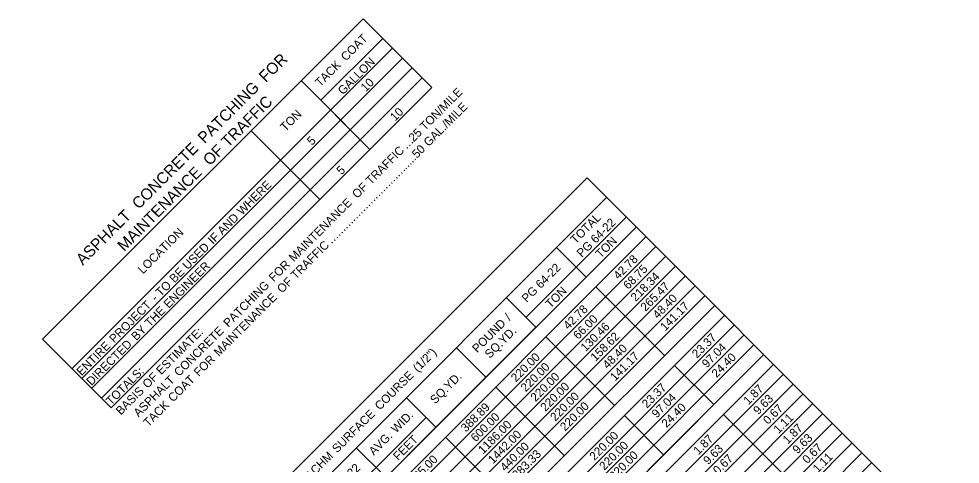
# Model space of a CAD drawing. Extents: x 1675667 to 1681231, y 227227 to 232694.
# Drawn here: x 1679139 to 1679800, y 230867 to 231180 of the extents above; entities that cross this region are included whole.
import ezdxf

# ---------------------------------------------------------------- set-up
doc = ezdxf.new("R2010")
doc.units = 0
doc.layers.add('Default', color=7, linetype='Continuous')

msp = doc.modelspace()

# ---------------------------------------------------------------- linework, layer by layer
at = {"layer": 'Default'}
for p, q in [((1679156.05, 230954.8), (1679381.12, 231179.93)), ((1679429.39, 231131.68), (1679381.12, 231179.93)), ((1679394.91, 231166.14), (1679381.12, 231179.93)), ((1679351.48, 231122.7), (1679394.91, 231166.14)), ((1679176.73, 230934.12), (1679401.8, 231159.25)), ((1679415.59, 231145.46), (1679401.8, 231159.25)), ((1679183.63, 230927.23), (1679408.7, 231152.36)), ((1679190.52, 230920.34), (1679415.59, 231145.46)), ((1679197.42, 230913.44), (1679422.49, 231138.57)), ((1679385.96, 231088.24), (1679337.69, 231136.49)), ((1679429.39, 231131.68), (1679422.49, 231138.57)), ((1679204.31, 230906.55), (1679429.39, 231131.68)), ((1679385.96, 231088.24), (1679351.48, 231122.7)), ((1679350.8, 231053.07), (1679302.53, 231101.33)), ((1679350.8, 231053.07), (1679323.22, 231080.65)), ((1678525.01, 230054.56), (1679538.35, 231068.14)), ((1679800.36, 230806.19), (1679538.35, 231068.14)), ((1679800.36, 230806.19), (1679538.35, 231068.14)), ((1678778.69, 230280.72), (1679552.14, 231054.36)), ((1679495.62, 230970.24), (1679565.93, 231040.57)), ((1678559.49, 230020.09), (1679572.82, 231033.68)), ((1679432.2, 230893.02), (1679572.82, 231033.68)), ((1678566.38, 230013.2), (1679579.72, 231026.78)), ((1678573.28, 230006.31), (1679586.61, 231019.89)), ((1679537.67, 230998.51), (1679516.98, 231019.19)), ((1678580.17, 229999.41), (1679593.51, 231013)), ((1678587.07, 229992.52), (1679600.4, 231006.1)), ((1678593.96, 229985.63), (1679607.3, 230999.21)), ((1678600.86, 229978.73), (1679614.2, 230992.32)), ((1679592.83, 230943.36), (1679544.56, 230991.62)), ((1679592.83, 230943.36), (1679544.56, 230991.62)), ((1678607.75, 229971.84), (1679621.09, 230985.42)), ((1679502.51, 230963.35), (1679481.83, 230984.03)), ((1678614.65, 229964.94), (1679627.99, 230978.53)), ((1678614.65, 229964.94), (1679627.99, 230978.53)), ((1678621.54, 229958.05), (1679634.88, 230971.64)), ((1678628.44, 229951.16), (1679641.78, 230964.74)), ((1678635.33, 229944.26), (1679648.67, 230957.85)), ((1679204.31, 230906.55), (1679156.05, 230954.8)), ((1679204.31, 230906.55), (1679156.05, 230954.8)), ((1679557.67, 230908.2), (1679509.41, 230956.45)), ((1679557.67, 230908.2), (1679509.41, 230956.45)), ((1678642.23, 229937.37), (1679655.57, 230950.96)), ((1679411.51, 230913.7), (1679446.67, 230948.86)), ((1679467.35, 230928.18), (1679446.67, 230948.86)), ((1678649.12, 229930.48), (1679662.46, 230944.06)), ((1679592.15, 230873.73), (1679662.46, 230944.06)), ((1678656.02, 229923.58), (1679669.36, 230937.17)), ((1679627.3, 230908.9), (1679599.72, 230936.47)), ((1679627.3, 230908.9), (1679599.72, 230936.47)), ((1678662.91, 229916.69), (1679676.25, 230930.28)), ((1678669.81, 229909.8), (1679683.15, 230923.38)), ((1678676.71, 229902.9), (1679690.04, 230916.49)), ((1679522.52, 230873.03), (1679474.25, 230921.29)), ((1679522.52, 230873.03), (1679474.25, 230921.29)), ((1678683.6, 229896.01), (1679696.94, 230909.6)), ((1679432.2, 230893.02), (1679411.51, 230913.7)), ((1678690.5, 229889.12), (1679703.83, 230902.7)), ((1679696.26, 230839.96), (1679634.2, 230902)), ((1679696.26, 230839.96), (1679634.2, 230902)), ((1678697.39, 229882.22), (1679710.73, 230895.81)), ((1679354.99, 230829.58), (1679425.3, 230899.91)), ((1679432.2, 230893.02), (1679425.3, 230899.91)), ((1679592.15, 230873.73), (1679564.57, 230901.31)), ((1679592.15, 230873.73), (1679564.57, 230901.31)), ((1678704.29, 229875.33), (1679717.62, 230888.92)), ((1679291.57, 230752.36), (1679432.2, 230893.02)), ((1678711.18, 229868.44), (1679724.52, 230882.02)), ((1679487.36, 230837.87), (1679439.09, 230886.12)), ((1679487.36, 230837.87), (1679439.09, 230886.12)), ((1679397.04, 230857.85), (1679376.36, 230878.53)), ((1678718.08, 229861.54), (1679731.41, 230875.13)), ((1679556.99, 230838.57), (1679592.15, 230873.73)), ((1679661.1, 230804.8), (1679731.41, 230875.13)), ((1678724.97, 229854.65), (1679738.31, 230868.24))]:
    msp.add_line(p, q, dxfattribs=at)

# ---------------------------------------------------------------- texts
for s, height, p in [(' COAT', 6, (1679367.49, 231148.26)), (' FOR', 8, (1679310.67, 231132.76)), ('GALLON', 6, (1679366.97, 231126.1)), ('TACK', 6, (1679351.04, 231131.81)), (' PATCHING', 8, (1679267.68, 231089.76)), ('10', 6, (1679382.98, 231128.33)), (' TON/MILE', 6, (1679423.03, 231099.44)), (' TRAFFIC', 8, (1679284.19, 231086.98)), (' GAL./MILE', 6, (1679425.59, 231088.21)), ('TON', 6, (1679326.56, 231100.43)), ('10', 6, (1679403.67, 231107.65)), ('25', 6, (1679416.68, 231093.08)), ('5', 6, (1679345.31, 231090.65)), ('…', 6, (1679411.45, 231087.85)), (' CONCRETE', 8, (1679221.52, 231043.6)), (' OF', 8, (1679271.39, 231074.17)), (' TRAFFIC', 6, (1679385.01, 231061.41)), ('.....50', 6, (1679411.06, 231073.67)), ('MAINTENANCE', 8, (1679213.38, 231016.15)), ('5', 6, (1679365.97, 231069.94)), ('…', 6, (1679405.82, 231068.44)), ('…', 6, (1679400.59, 231063.2)), (' WHERE', 6, (1679294.65, 231039.98)), (' OF', 6, (1679375.4, 231051.8)), ('…', 6, (1679395.36, 231057.97)), (' MAINTENANCE', 6, (1679330.93, 231007.31)), ('…', 6, (1679390.13, 231052.74)), ('…', 6, (1679379.67, 231042.27)), ('…', 6, (1679384.9, 231047.5)), ('ASPHALT', 8, (1679184.36, 231006.42)), (' AND', 6, (1679280.81, 231026.13)), ('…', 6, (1679374.44, 231037.04)), ('TOTAL', 6, (1679530.34, 231021.42)), ('…', 6, (1679369.2, 231031.81)), (' 64-22', 6, (1679542.88, 231020.17)), ('LOCATION', 6, (1679226.52, 231000.36)), (' IF', 6, (1679274.17, 231019.49)), ('…', 6, (1679363.97, 231026.57)), (' USED', 6, (1679256.37, 231001.68)), (' TRAFFIC', 6, (1679332.3, 230994.9)), ('…', 6, (1679358.74, 231021.34)), ('PG', 6, (1679534.67, 231011.96)), ('TON', 6, (1679547.9, 231011.4)), (' ENGINEER', 6, (1679243.04, 230974.56)), (' FOR', 6, (1679316.85, 230993.23)), (' 64-22', 6, (1679504.27, 230988.45)), ('42.78', 6, (1679560.43, 230996.35)), (' BE', 6, (1679247.13, 230992.44)), ('68.75', 6, (1679567.31, 230989.44)), ('218.34', 6, (1679572.58, 230980.93)), (' TO', 6, (1679237.52, 230982.83)), (' PATCHING', 6, (1679284.95, 230961.32)), (' OF', 6, (1679322.7, 230985.29)), ('265.47', 6, (1679579.47, 230974.03)), ('PG', 6, (1679496.07, 230980.24)), ('TON', 6, (1679512.74, 230976.24)), (' PROJECT', 6, (1679204.89, 230950.19)), (' -', 6, (1679234.08, 230979.4)), (' MAINTENANCE', 6, (1679278.22, 230940.8)), ('48.40', 6, (1679588.02, 230968.79)), ('141.17', 6, (1679593.26, 230960.24)), (' THE', 6, (1679229.86, 230961.38)), ('42.78', 6, (1679525.27, 230961.19)), ('POUND', 6, (1679461.32, 230944.96)), (' /', 6, (1679482.44, 230966.08)), ('66.00', 6, (1679532.18, 230954.3)), (' BY', 6, (1679220.35, 230951.86)), (' ESTIMATE:', 6, (1679237.81, 230927.96)), (' CONCRETE', 6, (1679250.35, 230926.72)), ('SQ.YD.', 6, (1679470.05, 230940.96)), ('130.46', 6, (1679537.42, 230945.75)), ('158.62', 6, (1679544.34, 230938.88)), ('23.37', 6, (1679615.59, 230941.21)), ('ENTIRE', 6, (1679183.47, 230928.77)), ('DIRECTED', 6, (1679190.36, 230921.87)), (' (1/2")', 6, (1679418.03, 230929.77)), ('48.40', 6, (1679552.86, 230933.62)), ('97.04', 6, (1679622.5, 230934.32)), (' FOR', 6, (1679264.15, 230926.72)), ('220.00', 6, (1679488.48, 230924.38)), ('141.17', 6, (1679558.1, 230925.07)), ('24.40', 6, (1679629.39, 230927.43)), ('220.00', 6, (1679495.37, 230917.49)), ('TOTALS:', 6, (1679204.15, 230908.09)), ('ASPHALT', 6, (1679223.46, 230899.82)), (' OF', 6, (1679228.2, 230918.35)), (' COAT', 6, (1679246.15, 230908.73)), (' COURSE', 6, (1679391.32, 230903.05)), ('SQ.YD.', 6, (1679431.71, 230908.97)), ('220.00', 6, (1679502.27, 230910.6)), ('220.00', 6, (1679509.16, 230903.7)), ('23.37', 6, (1679580.44, 230906.04)), ('1.87', 6, (1679651.72, 230908.39)), ('BASIS', 6, (1679211.05, 230901.19)), ('220.00', 6, (1679516.06, 230896.81)), ('97.04', 6, (1679587.34, 230899.16)), ('9.63', 6, (1679658.61, 230901.49)), ('TACK', 6, (1679230.36, 230892.92)), ('388.89', 6, (1679453.31, 230889.21)), ('220.00', 6, (1679522.96, 230889.92)), ('24.40', 6, (1679594.23, 230892.26)), ('0.67', 6, (1679665.51, 230894.6)), (' SURFACE', 6, (1679361.32, 230873.03)), (' WID.', 6, (1679402.79, 230886.94)), ('600.00', 6, (1679460.22, 230882.33)), ('1.11', 6, (1679672.81, 230888.12)), ('1186.00', 6, (1679465.47, 230873.78)), ('1.87', 6, (1679679.3, 230880.81)), ('1442.00', 6, (1679472.36, 230866.89)), ('220.00', 6, (1679543.64, 230869.24)), ('AVG.', 6, (1679388.71, 230872.85)), ('FEET', 6, (1679405.78, 230869.24)), ('440.00', 6, (1679480.9, 230861.64)), ('220.00', 6, (1679550.54, 230862.34)), ('1.87', 6, (1679616.56, 230873.22)), ('9.63', 6, (1679686.19, 230873.92)), ('0.67', 6, (1679693.09, 230867.03)), ('ACHM', 6, (1679343.96, 230855.67)), ('1283.33', 6, (1679486.14, 230853.1)), ('220.00', 6, (1679557.43, 230855.45)), ('9.63', 6, (1679623.45, 230866.33)), ('35.00', 6, (1679419.81, 230855.7)), ('0.67', 6, (1679630.35, 230859.43)), ('1.11', 6, (1679700.39, 230860.54)), (' 64-22', 6, (1679363.65, 230847.79))]:
    msp.add_text(s, height=height, rotation=45.00703, dxfattribs=at).set_placement(p)

doc.saveas('drawing.dxf')
